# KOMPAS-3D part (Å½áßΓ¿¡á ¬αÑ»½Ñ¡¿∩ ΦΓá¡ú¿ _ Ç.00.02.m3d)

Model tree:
1. Эскиз:1
2. Операция выдавливания:2
     Расстояние 1 = 5
3. Эскиз:4
4. Вырезать элемент выдавливания:2
     Расстояние 1 = 5

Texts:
  Пластина крепления штанги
